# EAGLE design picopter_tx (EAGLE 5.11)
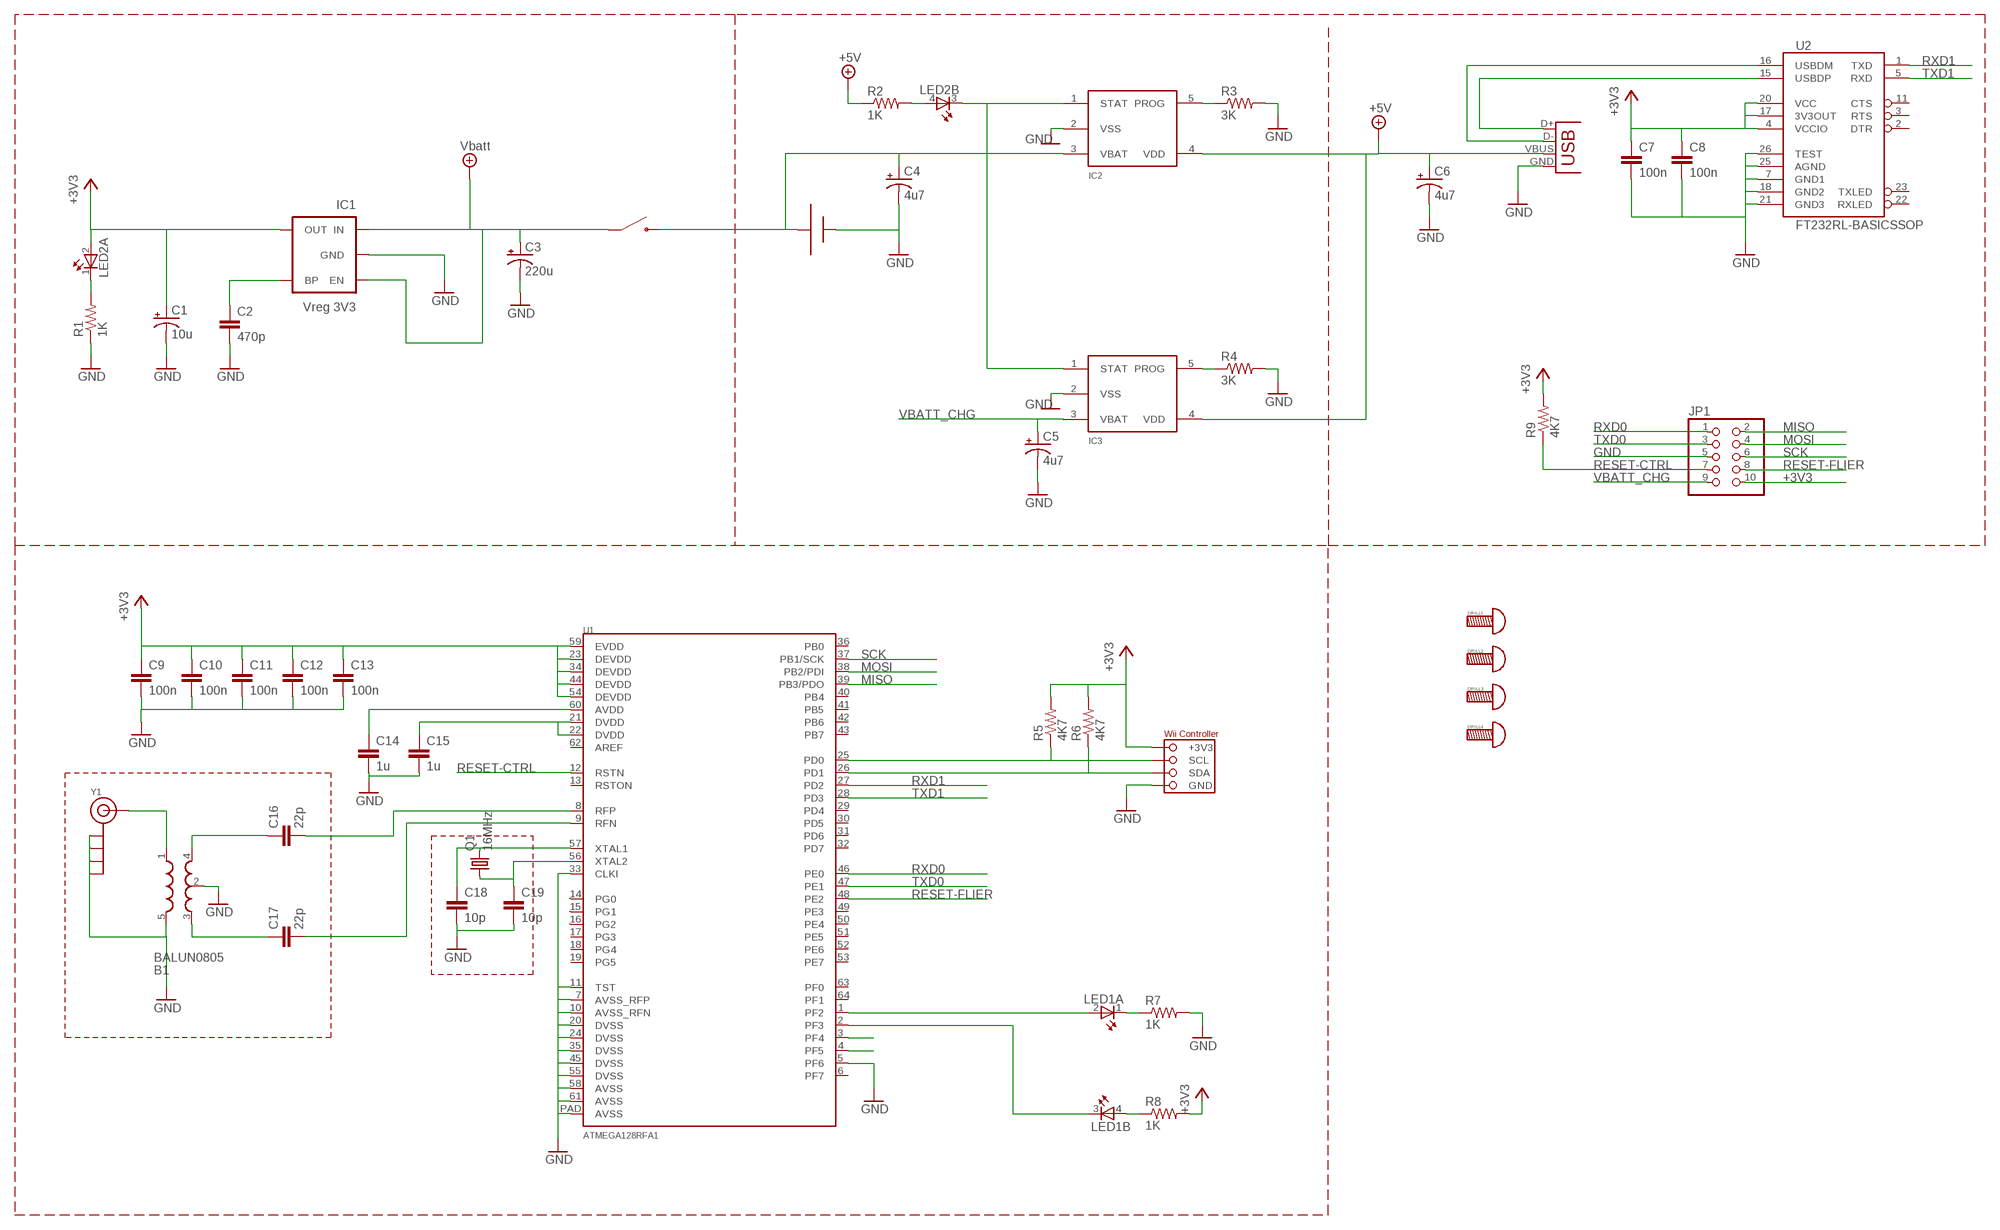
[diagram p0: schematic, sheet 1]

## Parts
B1  BALUN0805  [BALUN]
BATT2  BATT-CONNJST-PH-90  [JST-PH-2-90]
C1  10u  CPOL-USSMCB  [SMC_B]
C2  470p  C-EUC0603  [C0603]
C3  220u  CPOL-USSMCB  [SMC_B]
C4  4u7  CPOL-USSMCB  [SMC_B]
C5  4u7  CPOL-USSMCB  [SMC_B]
C6  4u7  CPOL-USSMCB  [SMC_B]
C7  100n  C-EUC0603  [C0603]
C8  100n  C-EUC0603  [C0603]
C9  100n  C-EUC0603  [C0603]
C10  100n  C-EUC0603  [C0603]
C11  100n  C-EUC0603  [C0603]
C12  100n  C-EUC0603  [C0603]
C13  100n  C-EUC0603  [C0603]
C14  1u  C-EUC0603  [C0603]
C15  1u  C-EUC0603  [C0603]
C16  22p  C-EUC0603  [C0603]
C17  22p  C-EUC0603  [C0603]
C18  10p  C-EUC0603  [C0603]
C19  10p  C-EUC0603  [C0603]
DRILL1  HOLE-4-40  [HOLE-4-40]
DRILL2  HOLE-4-40  [HOLE-4-40]
DRILL3  HOLE-4-40  [HOLE-4-40]
DRILL4  HOLE-4-40  [HOLE-4-40]
IC1  Vreg 3V3  V_REG_LDOSMD  [SOT23-5]
IC2  MCP-LI-CHARGER-1  [SOT23-5]
IC3  MCP-LI-CHARGER-1  [SOT23-5]
JP1  PINHD-2X5EDGE  [2X5-EDGE]
LED1  TOPLED-2-CUSTOM  [TOPLED2CUSTOM]
LED2  TOPLED-2-CUSTOM  [TOPLED2CUSTOM]
Q1  16MHz  CRYSTALCTS406  [CTS406]
R1  1K  R-US_R0603  [R0603]
R2  1K  R-US_R0603  [R0603]
R3  3K  R-US_R0603  [R0603]
R4  3K  R-US_R0603  [R0603]
R5  4K7  R-US_R0603  [R0603]
R6  4K7  R-US_R0603  [R0603]
R7  1K  R-US_R0603  [R0603]
R8  1K  R-US_R0603  [R0603]
R9  4K7  R-US_R0603  [R0603]
S1  SWITCH-PWR-CNKOS2  [SWITCH-SPDT-CNK-OS2]
U1  ATMEGA128RFA1  [QFN-64]
U2  FT232RL-BASICSSOP  [SSOP28DB]
USB  USB-SMD-NS  [USB-MINIB-NOSTOP]
X11  WII-CONN  [WII-CONN-2]
Y1  SMA_EDGE  [SMA-EDGE]

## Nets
+3V3: C1.+ C7.1 C8.1 C9.1 C10.1 C11.1 C12.1 C13.1 IC1.5(OUT) JP1.10 LED2.2(A:A) R5.2 R6.2 R8.2 R9.2 U1.23(DEVDD) U1.34(DEVDD) U1.44(DEVDD) U1.54(DEVDD) U1.59(EVDD) U2.4(VCCIO) U2.17(3V3OUT) U2.20(VCC) X11.+3V3
GND: B1.2(GND) B1.5(GND) BATT2.N C1.- C2.2 C3.- C4.- C5.- C6.- C7.2 C8.2 C9.2 C10.2 C11.2 C12.2 C13.2 C14.2 C15.2 C18.2 C19.2 IC1.2(GND) IC2.2(VSS) IC3.2(VSS) JP1.5 R1.1 R3.2 R4.2 R7.2 U1.5(PF6) U1.7(AVSS_RFP) U1.10(AVSS_RFN) U1.11(TST) U1.20(DVSS) U1.24(DVSS) U1.33(CLKI) U1.35(DVSS) U1.45(DVSS) U1.55(DVSS) U1.58(AVSS) U1.61(AVSS) U1.PAD(AVSS) U2.7(GND1) U2.18(GND2) U2.21(GND3) U2.25(AGND) U2.26(TEST) USB.GND X11.GND Y1.GND@0(GND) Y1.GND@1(GND) Y1.GND@2(GND) Y1.GND@3(GND)
MISO: JP1.2 U1.39(PB3/PDO)
MOSI: JP1.4 U1.38(PB2/PDI)
N$1: LED1.2(A:A) U1.1(PF2)
N$2: LED1.1(A:C) R7.1
N$3: LED1.4(B:A) R8.1
N$4: LED2.4(B:A) R2.2
N$6: U1.14(PG0)
N$7: U1.15(PG1)
N$8: U1.16(PG2)
N$9: LED2.1(A:C) R1.2
N$11: IC2.5(PROG) R3.1
N$15: IC3.5(PROG) R4.1
N$17: U2.16(USBDM) USB.D-
N$18: U2.15(USBDP) USB.D+
N$21: U1.3(PF4)
N$22: U1.4(PF5)
N$25: C2.1 IC1.4(BP)
N$26: C15.1 U1.21(DVDD) U1.22(DVDD)
N$27: C14.1 U1.60(AVDD)
N$28: B1.1(IN) Y1.SIG(SIGNAL)
N$29: B1.3(OUT1) C17.1
N$30: B1.4(OUT2) C16.1
N$31: C16.2 U1.8(RFP)
N$32: C17.2 U1.9(RFN)
N$33: C18.1 Q1.3 U1.57(XTAL1)
N$34: C19.1 Q1.1 U1.56(XTAL2)
N$38: IC2.1(STAT) IC3.1(STAT) LED2.3(B:C)
N$39: BATT2.P C4.+ IC2.3(VBAT) S1.2
N$41: LED1.3(B:C) U1.2(PF3)
RESET-CTRL: JP1.7 R9.1 U1.12(RSTN)
RESET-FLIER: JP1.8 U1.48(PE2)
RXD0: JP1.1 U1.46(PE0)
RXD1: U1.27(PD2) U2.1(TXD)
SCK: JP1.6 U1.37(PB1/SCK)
SCL: R5.1 U1.25(PD0) X11.SCL
SDA: R6.1 U1.26(PD1) X11.SDA
TXD0: JP1.3 U1.47(PE1)
TXD1: U1.28(PD3) U2.5(RXD)
VBATT: C3.+ IC1.1(IN) IC1.3(EN) S1.1 ; supply symbol labelled Vbatt
VBATT_CHG: C5.+ IC3.3(VBAT) JP1.9
VUSB: C6.+ IC2.4(VDD) IC3.4(VDD) R2.1 USB.VBUS ; supply symbol labelled +5V
Unconnected: U1.6(PF7) U1.13(RSTON) U1.17(PG3) U1.18(PG4) U1.19(PG5) U1.29(PD4) U1.30(PD5) U1.31(PD6) U1.32(PD7) U1.36(PB0) U1.40(PB4) U1.41(PB5) U1.42(PB6) U1.43(PB7) U1.49(PE3) U1.50(PE4) U1.51(PE5) U1.52(PE6) U1.53(PE7) U1.62(AREF) U1.63(PF0) U1.64(PF1) U2.2(DTR) U2.3(RTS) U2.11(CTS) U2.22(RXLED) U2.23(TXLED)

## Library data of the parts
B1 = palmquad_alpha:BALUN
BATT2 = palmquad_alpha:BATT-CONN
C1 C3-C6 = rcl:CPOL-US: POLARIZED CAPACITOR, American symbol
C2 C7-C19 = rcl:C-EU: CAPACITOR, European symbol
DRILL1-DRILL4 = palmquad_alpha:HOLE
IC1 = palmquad_alpha:V_REG_LDO: Voltage Regulator LDO Standard 150mA LDO voltage regulator in SOT-23 layout. Micrel part MIC5205. BP (by-pass) pin is used to lower output noise with 470pF cap.
IC2 IC3 = palmquad_alpha:MCP-LI-CHARGER-1
JP1 = palmquad_alpha:PINHD-2X5: PIN HEADER
LED1 LED2 = palmquad_alpha:TOPLED-2-: Multi TOPLED® (two color) LG T672, LP T672 LSY T67B LSW T67C LSY T675 LSY T676 LSG T677 LSG T770 Source: http://www.osram.convergy.de/
Q1 = palmquad_alpha:CRYSTAL: CRYSTAL; OC_FARNELL: unknown; OC_NEWARK: unknown
R1-R9 = rcl:R-US_: RESISTOR, American symbol
S1 = palmquad_alpha:SWITCH-PWR
U1 = palmquad_alpha:ATMEGA128RFA1
U2 = palmquad_alpha:FT232RL-BASIC: USB UART This is the simplified version of the FT232RL unit. Only what you need, nothing you don't. Spark Fun Electronics SKU : COM-00650
USB = palmquad_alpha:USB: USB Connectors USB-B-PTH is fully proven SKU : PRT-00139 USB-miniB is fully proven SKU : PRT-00587 USB-A-PCB is untested. USB-A-H is throughly reviewed, but untested. Spark Fun Electronics SKU : PRT-00437 USB-B-SMT is throughly reviewed, but untested. Needs silkscreen touching up. USB-A-S has not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
X11 = palmquad_alpha:WII-CONN
Y1 = palmquad_alpha:SMA_EDGE: SMA Antenna Connector End launch SMA connector. The paste layer has been removed so that the connector can be hand soldered onto the board after reflow.

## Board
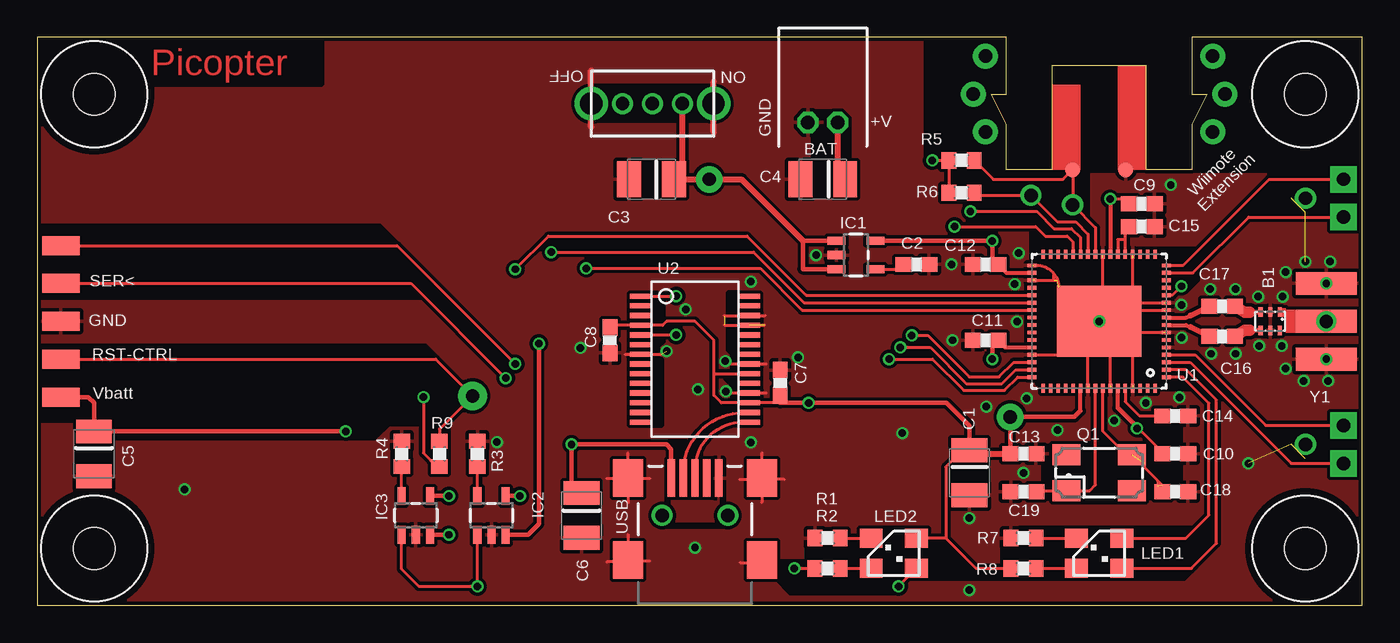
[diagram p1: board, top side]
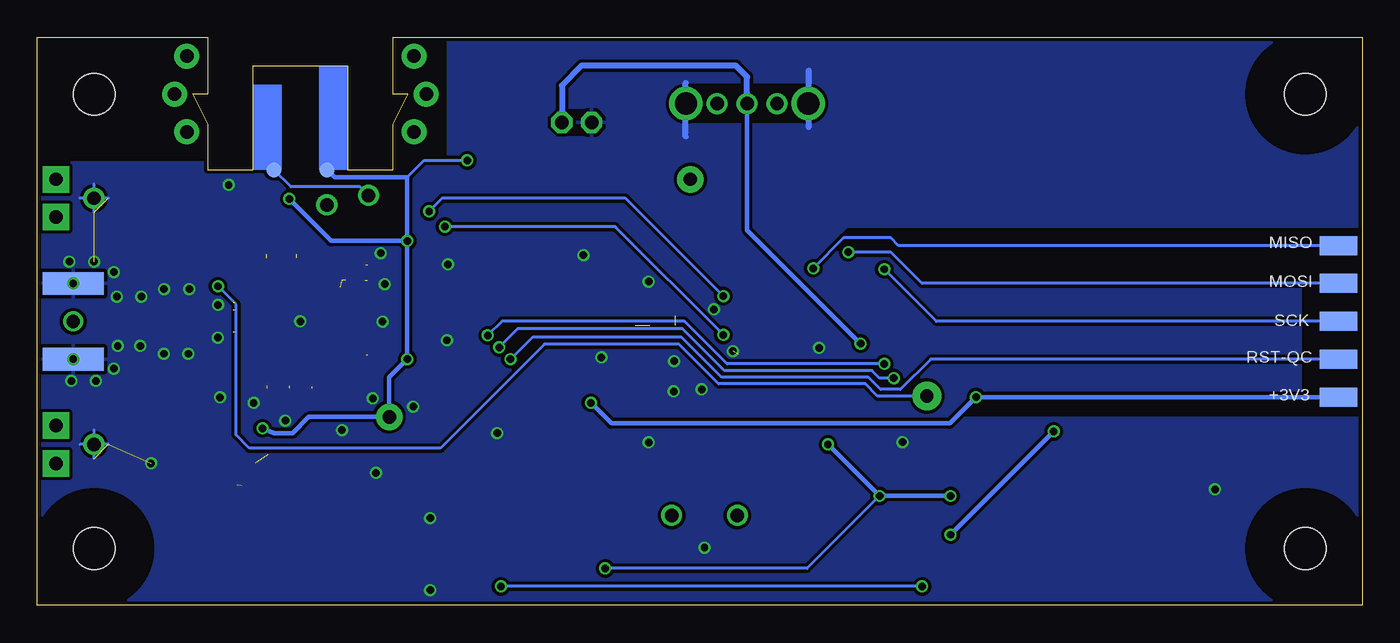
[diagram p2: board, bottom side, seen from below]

Size 88.9 x 38.1 mm. Coordinates in mm from the lower left corner, seen from the top.
Outline: 0,0 88.9,0 88.9,38.1 77.47,38.1 77.47,34.29 78.49,34.29 77.47,32.26 77.47,29.21 74.42,29.21 74.42,36.2 68.07,36.2 68.07,29.21 65.02,29.21 65.02,32.26 64.01,34.29 65.02,34.29 65.02,38.1 0,38.1 0,0
Copper layers (1*16): Top 0.035mm / dielectric 1.5mm / Bottom 0.035mm
Design rules "fusion_rules_tentedvias": minimum track width 6mil, minimum drill 0.3mm, track to track 7mil, track to pad 7mil, pad to pad 7mil, via to via 7mil, smd to smd 0mil, copper to edge 10mil, drill to drill 10mil, minimum pad ring 10mil, minimum via ring 6mil, stop-mask expansion 2mil, vias tented up to drill 25mil, thermal gap 10mil
tRestrict: area 67.1,14.9 to 75.4,23.2; 118 lines
bRestrict: 12 lines

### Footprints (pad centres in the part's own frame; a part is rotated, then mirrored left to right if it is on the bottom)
BALUN = smd 0.27 x 0.635: 1 -0.7,-0.616; 2 -0.05,-0.616; 3 0.6,-0.616; 4 0.6,0.616; 5 -0.05,0.616; 6 -0.7,0.616
JST-PH-2-90 = drill 0.9 pad 1.422 octagon: N -1,0; P 1,0
SMC_B = smd 1.6 x 2.4: + -1.5,0; - 1.5,0
C0603 = smd 1.1 x 1: 1 -0.85,0; 2 0.85,0
HOLE-4-40 = hole 2.794: 0,0
SOT23-5 = smd 0.55 x 1.2: 1 -0.95,-1.3; 2 0,-1.3; 3 0.95,-1.3; 4 0.95,1.3; 5 -0.95,1.3
2X5-EDGE = smd 2.54 x 1.27: 1 0,5.08; 3 0,2.54; 5 0,0; 7 0,-2.54; 9 0,-5.08 | smd 2.54 x 1.27 bottom: 2 0,5.08; 4 0,2.54; 6 0,0; 8 0,-2.54; 10 0,-5.08
TOPLED2CUSTOM = smd 1.27 x 1.524: 1 -1.016,-1.524; 2 -1.016,1.524; 3 1.016,1.524; 4 1.016,-1.524
CTS406 = smd 1.9 x 1.4: 1 -2.2,-1.2; 2 2.2,-1.2; 3 2.2,1.2; 4 -2.2,1.2
R0603 = smd 1 x 1.1: 1 -0.85,0; 2 0.85,0
SWITCH-SPDT-CNK-OS2 = drill 0.9 round: 1 0,2.007; 2 0,0; 3 0,-2.007 | drill 1.499 pad 1.905 round: P$4 0,4.102; P$5 0,-4.102
QFN-64 = smd 0.6 x 0.25: 1 -4.5,3.75; 2 -4.5,3.25; 3 -4.5,2.75; 4 -4.5,2.25; 5 -4.5,1.75; 6 -4.5,1.25; 7 -4.5,0.75; 8 -4.5,0.25; 9 -4.5,-0.25; 10 -4.5,-0.75; 11 -4.5,-1.25; 12 -4.5,-1.75; 13 -4.5,-2.25; 14 -4.5,-2.75; 15 -4.5,-3.25; 16 -4.5,-3.75; 33 4.5,-3.75; 34 4.5,-3.25; 35 4.5,-2.75; 36 4.5,-2.25; 37 4.5,-1.75; 38 4.5,-1.25; 39 4.5,-0.75; 40 4.5,-0.25; 41 4.5,0.25; 42 4.5,0.75; 43 4.5,1.25; 44 4.5,1.75; 45 4.5,2.25; 46 4.5,2.75; 47 4.5,3.25; 48 4.5,3.75 | smd 0.25 x 0.6: 17 -3.75,-4.5; 18 -3.25,-4.5; 19 -2.75,-4.5; 20 -2.25,-4.5; 21 -1.75,-4.5; 22 -1.25,-4.5; 23 -0.75,-4.5; 24 -0.25,-4.5; 25 0.25,-4.5; 26 0.75,-4.5; 27 1.25,-4.5; 28 1.75,-4.5; 29 2.25,-4.5; 30 2.75,-4.5; 31 3.25,-4.5; 32 3.75,-4.5; 49 3.75,4.5; 50 3.25,4.5; 51 2.75,4.5; 52 2.25,4.5; 53 1.75,4.5; 54 1.25,4.5; 55 0.75,4.5; 56 0.25,4.5; 57 -0.25,4.5; 58 -0.75,4.5; 59 -1.25,4.5; 60 -1.75,4.5; 61 -2.25,4.5; 62 -2.75,4.5; 63 -3.25,4.5; 64 -3.75,4.5 | smd 5.639 x 4.75: PAD 0,0
SSOP28DB = smd 0.348 x 1.397: 1 -4.225,-3.656; 2 -3.575,-3.656; 3 -2.925,-3.656; 4 -2.275,-3.656; 5 -1.625,-3.656; 6 -0.975,-3.656; 7 -0.325,-3.656; 8 0.325,-3.656; 9 0.975,-3.656; 10 1.625,-3.656; 11 2.275,-3.656; 12 2.925,-3.656; 13 3.575,-3.656; 14 4.225,-3.656; 15 4.225,3.656; 16 3.575,3.656; 17 2.925,3.656; 18 2.275,3.656; 19 1.625,3.656; 20 0.975,3.656; 21 0.325,3.656; 22 -0.325,3.656; 23 -0.975,3.656; 24 -1.625,3.656; 25 -2.275,3.656; 26 -2.925,3.656; 27 -3.575,3.656; 28 -4.225,3.656
USB-MINIB-NOSTOP = smd 2.5 x 0.5: D+ 2.5,0; D- 2.5,0.8; GND 2.5,-1.6; ID 2.5,-0.8; VBUS 2.5,1.6 | smd 2.5 x 2: G1 -3,-4.5; G2 -3,4.5; G3 2.5,4.5; G4 2.5,-4.5 | drill 0.9 pad 0.8 round: H1 0,2.2 | drill 0.9 pad 0.787 round: H2 0,-2.2
WII-CONN-2 = smd 1.016 x 1.016 bottom: +3V3 1.778,7.62; SDA -1.778,7.62 | smd 1.016 x 1.016: GND -1.778,7.62; SCL 1.778,7.62 | drill 0.9 pad 1.676 round: P$4 -7.62,0; P$5 7.62,0; P$6 -7.62,5.08; P$7 7.62,5.08; P$11 -8.445,2.54; P$12 8.445,2.54
SMA-EDGE = smd 1.524 x 4.064: GND@0 0,0; GND@1 5.08,0; SIG 2.54,0 | smd 1.524 x 4.064 bottom: GND@2 0,0; GND@3 5.08,0

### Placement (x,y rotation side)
B1  82.68,19.05 180 top
BATT2  52.7,32.38 0 top
C1  62.55,8.89 270 top
C2  58.99,22.86 0 top
C3  41.21,28.57 180 top
C4  52.7,28.57 180 top
C5  3.81,10.16 270 top
C6  36.51,6.03 270 top
C7  49.85,14.92 90 top
C8  38.42,17.78 270 top
C9  74.1,26.92 0 top
C10  76.35,10.16 0 top
C11  63.63,17.78 180 top
C12  63.63,22.86 180 top
C13  66.17,10.16 0 top
C14  76.35,12.7 0 top
C15  74.1,25.4 0 top
C16  79.5,18.03 180 top
C17  79.5,20.07 180 top
C18  76.35,7.62 0 top
C19  66.17,7.62 180 top
DRILL1  3.81,3.81 0 top
DRILL2  85.09,3.81 0 top
DRILL3  3.81,34.29 0 top
DRILL4  85.09,34.29 0 top
IC1  54.93,23.5 270 top
IC2  30.48,6.03 0 top
IC3  25.4,6.03 0 top
JP1  1.59,19.05 0 top
LED1  71.25,3.49 270 top
LED2  57.47,3.49 270 top
Q1  71.25,8.89 0 top
R1  53.02,4.51 0 top
R2  53.02,2.48 0 top
R3  29.53,10.16 90 top
R4  24.45,10.16 90 top
R5  62.01,29.84 180 top
R6  62.01,27.67 180 top
R7  66.17,4.51 180 top
R8  66.17,2.48 180 top
R9  26.99,10.16 270 top
S1  41.27,33.66 270 top
U1  71.25,19.05 180 top
U2  44.13,16.51 270 top
U$1  [MOCKQC]  not placed on the board
U$2  [PICOPTER-LOGO]  7.62,35.56 0 top
U$5  [ARM-MOCK]  not placed on the board
U$8  [ARM-MOCK]  not placed on the board
USB  44.13,6.03 90 top
X11  71.25,36.83 180 top
Y1  86.49,16.51 90 top

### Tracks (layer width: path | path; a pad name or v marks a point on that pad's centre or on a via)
+3V3  (via drill 0.5, 0.9 pad 1.78)
  Top 0.203: C13.1 65.29,10.19 | C13.1 65.32,10.23 | C10.1 75.48,10.27 73.73,12.01 73.53,12.01 | C13.1 65.28,10.16 | 64.07,17.38 C11.1 | v72,27.25 72.92,27.25 C9.1 | v60.06,29.84 R5.2 R6.2 | 60.96,4.51 60.96,9.29 62.06,10.39 C1.+ | C7.1 49.85,13.59 U2.17 45.9,13.59 45.4,14.08 45.4,15.54 | 45.4,15.54 U2.20 | C8.1 38.42,18.79 U2.4 41.96,18.79 42.23,19.05 44.13,19.05 45.4,17.78 45.4,15.54 | 60.96,4.51 LED2.2 | v25.91,13.97 25.91,10.2 26.8,9.31 R9.2 | R8.2 62.99,2.48 60.96,4.51
  Top 0.254: U1.34 65.04,22.3 C12.1 | 64.96,17.3 U1.44 | 70,13.03 U1.54 | 72.5,13.25 U1.59 | v72,27.25 U1.23
  Top 0.305: C11.1 64.96,17.3 | 72.5,13.25 73.73,12.01 73.79,11.96 v73.79,11.87 | 70,13.03 69.6,12.64 v65.28,12.64 65.28,10.16 | v64.07,16.51 64.07,17.38 | C12.1 64.07,23.27 v64.07,24.45 IC1.5 | 49.85,13.59 v51.75,13.59 61.01,13.59 62.55,12.05 C1.+
  Top 0.406: C13.1 62.78,10.16 C1.+
  Bottom 0.203: v60.06,29.84 62.93,29.84 64.07,28.7
  Bottom 0.305: X11.+3V3 68.96,28.7 64.07,28.7 v64.07,24.45 | v73.79,11.87 73.02,11.56 71.75,11.56 70.67,12.64 v65.28,12.64 65.28,15.3 v64.07,16.51 v64.07,24.45 | v64.07,24.45 69.19,24.45 v72,27.25 | JP1.10 v25.91,13.97 27.67,12.21 50.38,12.21 v51.75,13.59
GND  (via drill 0.5)  (20 unrouted)
  Top 0.203: 73.46,20.29 75.64,20.29 | 73.45,19.8 75.64,19.8 | 73.42,18.3 75.6,18.3 | 73.5,14.72 73.5,16.9 | 72,14.73 72,16.92 | 70.5,14.67 70.5,16.86 | 66.84,16.8 69.03,16.8 | 71.5,21.13 71.5,23.32 | 73.5,21.11 73.5,23.29 | 66.86,22.8 67.07,22.8 arc-90 68.53,21.34 | 66.9,21.8 68.45,21.8 | 68.21,21.82 68.21,22.24 | 50.1,8.45 49.47,8.45 | 48.64,9.59 48.64,10.22 | 47.12,8.45 47.75,8.45 | 47.18,2.86 47.82,2.86 | 40.45,2.98 41.08,2.98 | 38.86,2.92 38.23,2.92 | 39.62,4.76 39.62,4.13 | 39.62,7.49 39.62,6.86 | 40.45,8.51 41.08,8.51 | 38.23,8.51 38.86,8.51 | 39.62,9.59 39.62,10.22 | 48.61,7.53 48.61,6.89 | 39.47,16.83 41.85,16.83 | 46.51,16.19 48.9,16.19 | 46.51,14.26 48.9,14.26 | 46.1,18.8 48.8,18.8 | 46.1,19.43 48.83,19.43
  Top 0.406: 37.16,32.07 37.16,35.88 | 45.38,31.73 45.38,35.12
  Bottom 0.203: 85.09,9.84 85.09,11.75 | 84.14,10.79 86.04,10.79 | 84.14,27.3 86.04,27.3 | 85.09,26.35 85.09,28.26
  Bottom 0.406: 37.13,32.07 37.13,35.88 | 45.39,31.43 45.39,35.02
  other vias: 86.49,21.59 86.49,16.51 83.5,17.4 83.76,15.88 81.92,20.7 83.76,22.35 81.98,17.4 80.39,21.21 85.09,23.05 86.74,23.05 84.96,15.05 86.61,15.05 76.77,20.14 76.79,17.95 30.84,10.95 65.85,23.62 61.34,22.86 61.4,17.78 72.26,12.38 66.17,8.89 66.39,13.87 78.76,16.87 80.41,16.87 78.7,21.21 52.26,23.5 76.63,13.95 83.57,20.7 74.38,13.57 65.74,19.03 65.58,21.54 63.68,13.34 68.45,11.75 71.25,19.05 76.06,28.21 46.2,14.35 46.16,16.38 42.23,17.05 44.32,14.48 43.5,19.84 62.53,1.02 62.53,5.84 81.27,9.53 47.88,21.72 47.88,10.92 51.05,16.64 9.89,7.77 44.13,3.87 58.04,11.56 36.45,17.27
  pour Top (isolate 0.216): -0.32,38.42 89.22,38.42 89.22,-0.32 -0.32,-0.32
  pour Bottom (isolate 0.216): -0.32,38.42 89.22,38.42 89.22,-0.32 -0.32,-0.32
MISO  (via drill 0.5)
  Top 0.203: U1.39 51.32,19.8 48.51,22.61 v36.83,22.61
  Bottom 0.203: JP1.2 31.11,24.13 31.62,24.64 34.8,24.64 v36.83,22.61
MOSI  (via drill 0.5)
  Top 0.203: U1.38 51.45,20.3 48.07,23.69 v34.48,23.69
  Bottom 0.203: v34.48,23.69 31.62,23.69 29.53,21.59 JP1.4
N$1
  Top 0.203: U1.1 76.88,15.3 78.61,13.56 78.61,6.04 77.08,4.51 LED1.2
N$2
  Top 0.203: R7.1 LED1.1
N$3
  Top 0.203: R8.1 LED1.4
N$4
  Top 0.203: R2.2 LED2.4
N$7  (via drill 0.9 pad 1.78)
  Top 0.203: U1.15 77.55,22.3 81.28,26.04 v87.63,26.04
N$8  (via drill 0.9 pad 1.78)
  Top 0.203: U1.16 76.88,22.8 82.66,28.57 v87.63,28.57
N$9
  Top 0.203: R1.2 LED2.1
N$10  (via drill 0.9 pad 1.42)
  other vias: 85.09,10.79
N$11
  Top 0.203: IC2.5 R3.1
N$12  (via drill 0.9 pad 1.42)
  other vias: 85.09,27.3
N$15
  Top 0.203: IC3.5 R4.1
  Top 0.254: IC3.5
N$17
  Top 0.203: USB.D- 43.33,8.85 arc-90 47.42,12.94 U2.16
N$18
  Top 0.203: USB.D+ 44.13,9.06 arc-90 47.35,12.29 U2.15
N$21  (via drill 0.9 pad 1.78)
  Top 0.203: U1.3 77.36,16.3 84.14,9.53 v87.63,9.53
N$22  (via drill 0.9 pad 1.78)
  Top 0.203: U1.4 77.69,16.8 82.42,12.06 v87.63,12.06
N$25
  Top 0.203: IC1.4 58.14,22.55 C2.1
N$26
  Top 0.203: U1.21 73,24.52 | 73,24.52 73,25.4 C15.1 | U1.22 72.5,24.52 73,24.52
N$27
  Top 0.203: U1.60 73,13.66 73.96,12.7 C14.1
N$28  (via drill 0.9)
  Top 0.203: 85.99,19.55 Y1.SIG 85.87,19.67 B1.1
  other vias: 86.49,19.05
N$29
  Top 0.305: 81.36,19.67 B1.3
  Top 0.762: 81.36,19.67 81.01,19.67 C17.1
N$30
  Top 0.305: 81.36,18.43 B1.4
  Top 0.762: 81.36,18.43 81.01,18.43 C16.1
N$31
  Top 0.254: U1.8 77.08,18.8 77.37,18.68
  Top 0.406: 77.37,18.68 C16.2
N$32
  Top 0.254: U1.9 77.08,19.3 77.37,19.42
  Top 0.406: 77.37,19.42 C17.2
N$33  (2 unrouted)
  Top 0.203: U1.57 71.5,11.67 73.08,10.09 Q1.3 75.48,8.06 C18.1 | 74.3,9.53 74.3,9.27 | 75.18,8.33 75.18,8.03
N$34
  Top 0.203: Q1.1 69.4,7.69 | U1.56 71,8.08 70.61,7.7 Q1.1 | C19.1 67.09,7.69 Q1.1
N$38  (via drill 0.5)
  Top 0.203: v57.78,1.27 LED2.3 | IC3.1 24.45,2.41 25.59,1.27 v29.53,1.27 IC2.1
  Bottom 0.203: v29.53,1.27 v57.78,1.27
N$39  (via drill 0.5)
  Top 0.305: IC2.3 32.93,4.73 33.66,5.46 v33.66,17.55
  Top 0.406: C4.+ 53.7,29.07 BATT2.P
  Bottom 0.305: v33.66,17.55 40.37,24.27 41.27,25.17 S1.2
  Bottom 0.406: S1.2 41.27,35.44 42.03,36.2 52.37,36.2 53.7,34.86 BATT2.P
N$41
  Top 0.203: U1.2 77.1,15.8 79.12,13.78 79.12,4.15 77.44,2.48 LED1.3
RESET-CTRL  (via drill 0.5, 0.9 pad 1.93)
  Top 0.203: U1.12 76.17,20.8 v76.77,21.4 | JP1.7 26.73,16.51 v29.21,14.03 26.99,11.81 R9.1
  Bottom 0.203: v76.77,21.4 75.56,20.19 75.56,11.43 74.68,10.54 61.85,10.54 54.86,17.53 45.85,17.53 43.18,14.86 33.34,14.86 32.51,14.03 v29.21,14.03
RESET-FLIER  (via drill 0.5)
  Top 0.203: U1.48 65.78,15.3 64.9,14.41 62.17,14.41 60.07,16.51 v57.15,16.51
  Bottom 0.203: v57.15,16.51 55.67,17.99 45.68,17.99 42.99,15.3 33.15,15.3 32.32,14.48 30.99,14.48 28.96,16.51 JP1.8
RXD0  (via drill 0.5)
  Top 0.203: U1.46 65.51,16.3 64.53,15.32 62.53,15.32 59.75,18.1 v58.67,18.1 | v32.07,16.19 24.13,24.13 JP1.1
  Bottom 0.203: v32.07,16.19 42.61,16.19 45.47,19.05 57.72,19.05 v58.67,18.1
RXD1  (via drill 0.5)
  Top 0.203: U1.27 70,24.67 69.4,25.27 68.2,25.27 67.06,26.42 v62.61,26.42 | U2.1 v42.86,20.73
  Bottom 0.203: v42.86,20.73 49.43,27.3 61.72,27.3 v62.61,26.42
SCK  (via drill 0.5)
  Top 0.203: U1.37 51.59,20.8 47.62,24.77 34.29,24.77 v32.07,22.54
  Bottom 0.203: v32.07,22.54 28.57,19.05 JP1.6
SCL  (via drill 0.9 pad 1.42)
  Top 0.203: 62.86,29.8 R5.1 64.15,28.56 68.82,28.56 X11.SCL v69.47,26.86 71,25.33 U1.25
SDA  (via drill 0.9 pad 1.42)
  Top 0.203: U1.26 70.5,24.9 69.68,25.72 68.45,25.72 v66.67,27.5 63.04,27.5 R6.1
  Bottom 0.203: X11.SDA 71.88,28.07 67.25,28.07 v66.67,27.5
TXD0  (via drill 0.5)
  Top 0.203: U1.47 65.65,15.8 64.71,14.86 62.36,14.86 59.91,17.3 v57.91,17.3 | v31.43,15.24 25.08,21.59 JP1.3
  Bottom 0.203: v31.43,15.24 32.38,15.24 32.89,15.75 42.8,15.75 45.59,18.54 56.67,18.54 v57.91,17.3
TXD1  (via drill 0.5)
  Top 0.203: U1.28 69.5,24.38 69.11,24.77 67.63,24.77 66.99,25.4 v61.55,25.4 | U2.5 v42.86,18.14
  Bottom 0.203: v42.86,18.14 50.13,25.4 v61.55,25.4
VBATT  (via drill 0.9 pad 1.78)
  Top 0.305: IC1.1 51.37,24.45 51.37,22.55 IC1.3
  Top 0.406: S1.1 43.28,29.14 C3.+ v45.09,28.57 47.24,28.57 51.37,24.45
VBATT_CHG  (via drill 0.5)
  Top 0.305: JP1.9 3.42,13.97 3.81,13.58 C5.+ v20.7,11.66 | v27.62,4.73 IC3.3
  Bottom 0.305: v20.7,11.66 v27.62,4.73
VUSB  (via drill 0.5)
  Top 0.203: R2.1 52.17,2.5 52.13,2.48 v50.8,2.48
  Top 0.305: IC3.4 v27.62,7.33 | v32.38,7.33 IC2.4 | USB.VBUS 42.53,10.48 42.22,10.79 v35.85,10.79 35.85,7.53 C6.+
  Bottom 0.203: v50.8,2.48 37.24,2.48 v32.38,7.33
  Bottom 0.305: v27.62,7.33 v32.38,7.33 v35.85,10.79
(copper drawn outside any net)
  shapes: Top area x2

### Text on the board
_tsilk: OFF | ON | BAT | Wiimote | Extension | SER< | GND | RST-CTRL | Vbatt
_bsilk: MISO | MOSI | SCK | RST-QC | +3V3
